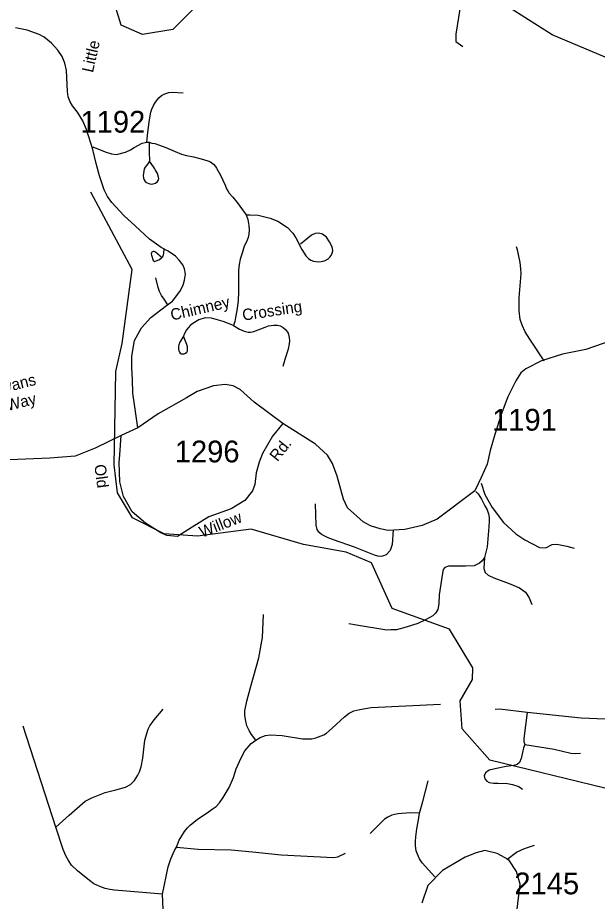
# Model space of a CAD drawing. Extents: x 884530 to 1028605, y 526725 to 653634.
# Drawn here: x 952140 to 955468, y 574776 to 579851 of the extents above; entities that cross this region are included whole.
import ezdxf

# ---------------------------------------------------------------- set-up
doc = ezdxf.new("R2010")
doc.units = 0
for name, color, linetype in [('Exist Hydrographic Creek Single Shore', 7, 'Continuous'), ('Exist Road Non-System Type 51', 7, 'Continuous'), ('Exist Road Non-System Type 51 Label', 7, 'Continuous'), ('Exist Road Secondary Type 41 Attributed', 7, 'Continuous'), ('Exist Road Secondary Type 51 Attributed', 7, 'Continuous'), ('Exist Road Secondary Type 51 Label', 7, 'Continuous'), ('Exist Road Secondary Type 51 Number Label', 7, 'Continuous')]:
    doc.layers.add(name, color=color, linetype=linetype)

msp = doc.modelspace()

# ---------------------------------------------------------------- linework, layer by layer
at = {"layer": 'Exist Hydrographic Creek Single Shore'}
for points in [[(955878.1, 579595.1), (955513.6, 579625.4), (955209.6, 579752.9), (954973.2, 579902.1), (954735.2, 580011.9), (954544.8, 580051.7), (954430.4, 580113.1), (954046.2, 580101.2), (953855.9, 580141.1), (953455.4, 580132.7), (953328.8, 580086.1), (953031.5, 579784.1), (952856.8, 579755.7), (952734, 579807.7), (952630.2, 580147.8), (952328, 580525.7), (951709.5, 580686.3), (951128.8, 580771.3)], [(955732, 575371.2), (954851.6, 575585.8), (954691.4, 575766.3), (954680.5, 575927.2), (954751.5, 576050.5), (954753.8, 576116.1), (954620.1, 576338.7), (954290.9, 576456.9), (954171.2, 576719.5), (954027.2, 576780.9), (953781.7, 576825.8), (953481.6, 576912.9), (953171.8, 576873.1), (952980.5, 576886.8), (952800.2, 576979.1), (952713.6, 577122), (952694.3, 577283.1), (952701.2, 577706.4), (952702.9, 577818.5), (952740.6, 577979.1), (952797.3, 578404.3), (952561.2, 578848.3)]]:
    msp.add_lwpolyline(points, dxfattribs=at)
at = {"layer": 'Exist Road Non-System Type 51'}
for p, q in [((952881.4, 579136.9), (952895, 579135.5)), ((952359.8, 575202.4), (952171.4, 575782.6))]:
    msp.add_line(p, q, dxfattribs=at)
for points in [[(952881.4, 579136.9), (952885.5, 579174.9), (952894.9, 579253.9), (952904.8, 579308), (952910.8, 579325.7), (952920.2, 579347.6), (952931.1, 579366.2), (952949.9, 579390.5), (952966.1, 579405.3), (952985.1, 579414.7), (953008, 579421.5), (953026.9, 579424.2), (953090.4, 579418.8)], [(952571.7, 579110.2), (952642.5, 579080.8), (952679.8, 579069), (952707.7, 579065.5), (952760, 579078.6), (952787.8, 579092.5), (952808.9, 579105.3), (952855.2, 579130.8), (952871.7, 579135.3), (952881.4, 579136.9)], [(952895, 579135.5), (952894.8, 579081.4), (952896.6, 579026.5), (952892.2, 579018.4), (952887.9, 579011.8), (952880.5, 579003.1), (952872.4, 578992.8), (952866.8, 578982.9), (952862, 578955.4), (952861.7, 578943.9), (952863.4, 578929.3), (952866, 578919.8), (952872.7, 578911.2), (952883, 578902.8), (952892.7, 578898.8), (952899.6, 578896.6), (952907.9, 578895.1), (952918, 578896.7), (952930.7, 578901.2), (952942.9, 578910.9), (952947, 578915.9), (952949.3, 578921.4), (952950.1, 578928.1), (952949.4, 578935.1), (952942.9, 578956.2), (952932.3, 578975.6), (952928.3, 578983.4), (952923.9, 578989.5), (952919.8, 578994.8), (952896.6, 579026.5)], [(952895, 579135.5), (952909.9, 579131.4), (952926.8, 579127.7), (952955, 579119.6), (952990.5, 579105.8), (953043.9, 579083.2), (953081.2, 579067.8), (953110, 579060.3), (953149.9, 579052.4), (953194.3, 579040.3), (953231.6, 579029.8), (953247.3, 579022.8), (953264.4, 579010.7), (953275.9, 578997.4), (953282.5, 578987.4), (953304.4, 578946.5), (953330.9, 578888.4), (953340, 578868.2), (953347.4, 578856.3), (953354.7, 578844.1), (953374.7, 578819.6), (953400.2, 578790.4), (953431.8, 578748.2), (953453, 578718.7)], [(953453, 578718.7), (953461.2, 578691.7), (953468.2, 578658.5), (953469.8, 578633.5), (953467, 578608.6), (953462.9, 578588.5), (953453.8, 578564.3), (953441.3, 578538.5), (953429.1, 578498.6), (953417.9, 578464.8), (953411.7, 578433.7), (953408.8, 578399.7), (953407.6, 578337.5), (953408, 578272.8), (953406.8, 578229.3), (953400.2, 578181), (953391.2, 578129), (953387.7, 578106.6), (953378.9, 578084)], [(953453, 578718.7), (953474.7, 578718.4), (953521.5, 578716.5), (953589.1, 578700.7), (953633.6, 578681.9), (953688.9, 578645.7), (953720.1, 578614.5), (953737.3, 578587.4), (953772.4, 578518.9), (953795.2, 578482.6), (953810.2, 578468), (953824, 578458.2), (953837.8, 578453), (953852.1, 578451.4), (953866.7, 578449.8), (953882.9, 578450.1), (953895.1, 578452.5), (953905.8, 578457.1), (953922, 578466.8), (953932.9, 578475.8), (953939.9, 578485), (953946, 578498.5), (953948.8, 578512.7), (953948.4, 578524.9), (953943.9, 578539.6), (953931.3, 578563.9), (953912.6, 578591.2), (953889.9, 578608.7), (953867.9, 578614.4), (953847.6, 578612.3), (953827.2, 578602.2), (953764.4, 578551.1)], [(952979.8, 578521.7), (952977.3, 578500.6), (952975.7, 578487.5), (952974.2, 578481.3), (952969.4, 578475.6), (952962.5, 578478.6), (952957.7, 578481.6), (952932, 578504), (952927.8, 578506.5), (952923.8, 578507.7), (952918.5, 578507.4), (952914.4, 578506.3), (952911.2, 578504.3), (952908.6, 578501.5), (952907.3, 578494.9), (952907.7, 578487.5), (952917.8, 578457.2), (952919.5, 578454), (952921.4, 578452.1), (952923.5, 578451.4), (952926.2, 578451), (952929.5, 578451.8), (952941.8, 578457.4), (952953.6, 578463.1), (952969.4, 578475.6)], [(955163.7, 577879.7), (955163.6, 577880), (955081.1, 578004.8), (955054.5, 578046.9), (955036.1, 578086), (955024.6, 578117.7), (955018.6, 578167), (955018.6, 578241.8), (955028.5, 578356.6), (955030.7, 578382.9), (955029.5, 578406.5), (955027, 578427.6), (955024.5, 578445.1), (955010.8, 578517.2), (955004.5, 578534.6)], [(953002.8, 578201), (952981.1, 578233.8), (952966, 578256.1), (952953.6, 578277.7), (952946.3, 578302), (952932.6, 578357.8)], [(953378.9, 578084), (953319.4, 578107), (953253.4, 578125.6), (953216.9, 578127.7), (953181, 578116.3), (953145.1, 578094.9), (953131.3, 578083.5), (953121.1, 578072.5), (953110.4, 578058), (953098, 578037.1), (953091.7, 578021.6), (953070.9, 577987.2), (953066, 577972.9), (953063.2, 577959.8), (953063.5, 577947.1), (953065.6, 577937.3), (953068.9, 577929.9), (953073, 577923.8), (953078.3, 577921.3), (953085.3, 577920.1), (953096.2, 577920.9), (953104.6, 577924.7), (953111.9, 577930.7), (953114.4, 577937.3), (953116, 577948), (953114.8, 577961.5), (953110.6, 577974.6), (953091.7, 578021.6)], [(953378.9, 578084), (953414.6, 578061.4), (953440.3, 578049.9), (953464.1, 578045), (953477.2, 578045.8), (953496.4, 578047.9), (953561.2, 578072.9), (953580.4, 578080.6), (953611.5, 578086), (953632.4, 578085.1), (953648, 578081), (953664.3, 578071.6), (953679.5, 578058.6), (953692.6, 578038.8), (953699.6, 578014.3), (953701.2, 577995.4), (953699.6, 577977.9), (953693.9, 577946.7), (953674.7, 577887.7), (953663.1, 577848)], [(954801.5, 577177.6), (954821.6, 577113.4), (954863.8, 577037.1), (954930, 576951.8), (955000.2, 576886.6), (955051.4, 576852.4), (955136.7, 576808.3), (955171.9, 576806.2), (955209, 576824.7), (955236.2, 576827.4), (955292.3, 576816.3), (955334.5, 576803.3)], [(954771.4, 577129.2), (954783.4, 577115.4), (954802.5, 577086.3), (954822.7, 577048.2), (954836.6, 577024), (954843.8, 577001), (954847.7, 576980), (954848.2, 576960.9), (954845.7, 576926.7), (954835.6, 576812.3), (954819.6, 576751.1)], [(954295.7, 576909.6), (954289.6, 576824.3), (954279.6, 576790.2), (954255.5, 576766.1), (954235.4, 576758.1), (954224.3, 576756), (954207.3, 576759.1), (954188.2, 576763.1), (954073.9, 576810.3), (953953.3, 576851.4), (953922.3, 576863.5), (953885.2, 576883.6), (953870.1, 576895.6), (953860.1, 576911.7), (953853.1, 576936.7), (953851, 577058.2)], [(954819.6, 576751.1), (954806.6, 576732), (954791.5, 576718), (954761.4, 576702.9), (954712.1, 576699.9), (954613.8, 576699.9), (954592.7, 576693.9), (954583.8, 576681.8), (954579.7, 576660.7), (954567.7, 576585.4), (954559.6, 576536.2), (954558.7, 576484), (954551.6, 576452), (954539.6, 576430.9), (954523.5, 576415.8), (954481.4, 576391.8), (954437.2, 576370.7), (954369.9, 576349.6), (954314.8, 576335.6), (954283.6, 576334.6), (954259.5, 576333.6), (954084.9, 576362.6), (954041.7, 576368.7)], [(954819.6, 576751.1), (954816.5, 576687.8), (954824.6, 576663.8), (954841.7, 576648.7), (954873.8, 576634.6), (954962.1, 576601.5), (955021.4, 576576.4), (955056.4, 576551.3), (955077.5, 576518.2), (955092.6, 576480)], [(953508.4, 575702.1), (953483, 575734.3), (953469.4, 575757.7), (953456.6, 575783.4), (953449.5, 575810.5), (953444.5, 575843.4), (953443.8, 575870.4), (953455.2, 575926), (953476.6, 576004.5), (953525.1, 576174.3), (953545.1, 576291.2), (953552.2, 576422.4)], [(953508.4, 575702.1), (953532.6, 575716.4), (953562.6, 575728.4), (953591.6, 575732.3), (953658.5, 575727.3), (953776.4, 575709.2), (953828.8, 575709.4), (953851.8, 575714.2), (953897.7, 575731.5), (953913.2, 575740.8), (953945.7, 575770.3), (954017.1, 575834.8), (954044.3, 575856.2), (954069.9, 575869), (954105.6, 575877.5), (954169.8, 575889), (954567.7, 575907.5)], [(952359.8, 575202.4), (952435.9, 575270.9), (952528.3, 575350.3), (952566.2, 575370.9), (952643.4, 575400.2), (952703.7, 575416.6), (952758.4, 575431.2), (952788.6, 575447.6), (952810.4, 575470.4), (952829.7, 575499.7), (952840.5, 575518.8), (952849.7, 575549), (952858.8, 575598.3), (952869.8, 575700.5), (952888.9, 575764.4), (952899.9, 575784.5), (952924.6, 575817.3), (952974.7, 575879.4)], [(955065.3, 575860.9), (954906.5, 575879.7), (954880.9, 575876.7)], [(955065.3, 575860.9), (955045.7, 575710), (955046.6, 575693.2), (955052.5, 575676.4)], [(955838.9, 575809.1), (955374.6, 575828.6), (955065.3, 575860.9)], [(953052.4, 575086.1), (953066.9, 575127.3), (953098.5, 575176.8), (953115.3, 575197.5), (953131.4, 575213.4), (953172.8, 575246.8), (953228.5, 575283.3), (953257.7, 575305.2), (953279.7, 575319.8), (953299.7, 575341.7), (953319.8, 575371.9), (953355.4, 575429.4), (953379.1, 575486.9), (953395.6, 575537.1), (953423, 575600.1), (953445.1, 575639.4), (953481.6, 575681.8), (953508.4, 575702.1)], [(955052.5, 575676.4), (955043.6, 575656.8), (955038.8, 575631.1), (955031.8, 575595.6), (955021.8, 575573.9), (955007.2, 575562), (954988.5, 575555.2), (954944, 575549.1), (954888.6, 575538.1), (954847.6, 575528.6), (954825.3, 575514.4), (954819.1, 575496.9), (954821.6, 575479.1), (954833.5, 575465.3), (954847.6, 575457.4), (954872, 575453.5), (954899.7, 575454.4), (954952, 575451.5), (954981.5, 575447.6), (955017.1, 575434.7), (955038.8, 575419.9)], [(955052.5, 575676.4), (955220.3, 575649.8), (955316, 575626.1), (955344.5, 575625.1), (955372.2, 575626.1)], [(954447.2, 575282.5), (954465.5, 575349.9), (954496.4, 575468.1)], [(954447.2, 575282.5), (954393.3, 575283.3), (954322.8, 575277.8), (954288.7, 575270.6), (954264.8, 575258.7), (954246.6, 575246.8), (954235.6, 575236.5), (954164.1, 575165.9)], [(954534.5, 574916.9), (954463.1, 574996.2), (954448, 575020), (954436.1, 575046.2), (954429, 575066), (954425.1, 575093.7), (954425, 575118.4), (954426.6, 575146.1), (954432.1, 575192.1), (954440.1, 575232.6), (954447.2, 575282.5)], [(952971.9, 574816.1), (952696.2, 574840.4), (952669, 574843.7), (952641.9, 574849.3), (952612, 574860.1), (952576.9, 574875.9), (952551.7, 574895.1), (952484.5, 574949.8), (952449.4, 574983), (952432.1, 575010.5), (952417.6, 575036.7), (952402.2, 575073.6), (952359.8, 575202.4)], [(954948.5, 575016.4), (955003.9, 575057.2), (955050.6, 575078.7), (955108.1, 575098.4)], [(952971.9, 574816.1), (953004.7, 574974.4), (953020.4, 575020.4), (953040.5, 575067.9), (953052.4, 575086.1)], [(953052.4, 575086.1), (953175.6, 575075.2), (953365.2, 575070.6), (953489.4, 575060.1), (953652.1, 575042.6), (953953.1, 575026.9), (953977.9, 575030.4), (954023.2, 575053.1)], [(953033.6, 574314.8), (953036.4, 574361.2), (953017.7, 574462.3), (953003.1, 574526.8), (952989.2, 574597.4), (952980.8, 574653.5), (952975.1, 574729.2), (952971.9, 574816.1)]]:
    msp.add_lwpolyline(points, dxfattribs=at)
at = {"layer": 'Exist Road Secondary Type 41 Attributed'}
for points in [[(952571.8, 579093.5), (952534.7, 579210), (952514.2, 579259.4), (952483.1, 579308.7), (952455.8, 579345.5), (952441.4, 579368.3), (952430.7, 579397.1), (952426.9, 579427.5), (952420.1, 579548.9), (952411.8, 579590.3), (952395.8, 579629), (952371.6, 579663.9), (952333.6, 579704.1), (952292.7, 579739), (952264.1, 579755), (952194.8, 579778.9), (952128, 579793.3)], [(953662, 577519.6), (953604.1, 577447.3), (953545.3, 577347.6), (953526.2, 577297.4), (953509.9, 577236.5), (953502, 577169.8), (953488.1, 577133.3), (953444.9, 577077.3), (953366, 577029.5), (953236.9, 576984), (953141.3, 576924.2), (953057.6, 576871.6), (952996.8, 576877.9), (952962, 576893.1), (952875, 576947.4), (952797.1, 577012.7), (952746.9, 577101.2), (952727.7, 577184.5), (952723, 577297.1), (952726, 577339.6), (952734.8, 577451)]]:
    msp.add_lwpolyline(points, dxfattribs=at)
at = {"layer": 'Exist Road Secondary Type 51 Attributed'}
msp.add_line((952830.5, 577496.2), (952734.8, 577451), dxfattribs=at)
for points in [[(954684.7, 579936), (954655.9, 579756.1), (954656.2, 579714.1), (954696.9, 579686.3)], [(952830.5, 577496.2), (952812.3, 577616.2), (952801.7, 577693.6), (952798.7, 577772.5), (952795.6, 577839.3), (952795.6, 577907.6), (952810.8, 577997.9), (952851.8, 578069.7), (952904.9, 578128.9), (952994.4, 578197.2), (953029.3, 578222.6), (953071.5, 578277.6), (953090.8, 578315.2), (953098.4, 578344), (953102.9, 578378.2), (953097.6, 578407.8), (953088.5, 578432.4), (953067.5, 578458), (953046, 578481.8), (953005.1, 578510.3), (952964.1, 578531.9), (952896.6, 578579.7), (952814.1, 578655.6), (952749.4, 578715.5), (952680.3, 578789.2), (952656.1, 578824.8), (952637.2, 578862.7), (952610.5, 578943.6), (952590.8, 579014.2), (952571.8, 579093.5)], [(955738.9, 578061.6), (955402.4, 577945.2), (955267.7, 577918), (955147.9, 577880.9), (955058.1, 577834.2), (955030, 577811.1), (954999.9, 577765.8), (954955.1, 577673.5), (954916.9, 577571.9), (954879.2, 577457.1), (954853, 577364.4), (954835, 577287.3), (954802, 577209.2), (954765, 577133.9), (954548.9, 576969.9), (954462.7, 576934.4), (954362.4, 576910.8), (954267.9, 576906.1), (954220.7, 576915.6), (954166.4, 576932.1), (954124, 576955.7), (954034.2, 577036), (954010.6, 577085.6), (953975.2, 577217.9), (953946.9, 577291.1), (953918.6, 577338.3), (953850.1, 577402.1), (953662, 577519.6)], [(953662, 577519.6), (953587.9, 577575), (953498.3, 577642.8), (953417.7, 577714.8), (953378.3, 577736.1), (953331.3, 577743.7), (953264.5, 577737.6), (953170.4, 577704.2), (953110.1, 577667.7), (952947.2, 577575.6), (952830.5, 577496.2)], [(952734.8, 577451), (952585, 577377.9), (952471.1, 577332.3), (952325.4, 577320.9), (952045.4, 577309.5)], [(955004.5, 574699.2), (955025.7, 574873.9), (955004.5, 574947.2), (954959.6, 575013.3), (954893.5, 575051.1), (954822.7, 575067.6), (954773.1, 575053.4), (954709.4, 575029.8), (954579.5, 574951.9), (954494.6, 574867.3), (954461.5, 574765.3)]]:
    msp.add_lwpolyline(points, dxfattribs=at)

# ---------------------------------------------------------------- texts
at = {"layer": 'Exist Road Non-System Type 51 Label'}
for s, rotation, p in [('Little', 77.2848, (952572.1, 579532.4)), ('Chimney', 12.9987, (953025.8, 578111.1)), ('Crossing', 8.749, (953434.9, 578110.4)), ('Evans', 14.0407, (952014, 577684.4)), ('Way', 14.0407, (952082.1, 577591.4))]:
    msp.add_text(s, height=65.62, rotation=rotation, dxfattribs=at).set_placement(p)
at = {"layer": 'Exist Road Secondary Type 51 Label'}
for s, rotation, p in [('Rd.', 51.4011, (953631.6, 577297.8)), ('Old', 277.5524, (952579.9, 577281.3)), ('Willow', 21.4984, (953198.6, 576863.5))]:
    msp.add_text(s, height=65.62, rotation=rotation, dxfattribs=at).set_placement(p)
at = {"layer": 'Exist Road Secondary Type 51 Number Label'}
for s, p in [('1192', (952500.9, 579191.1)), ('1191', (954864, 577479.3)), ('1296', (953042.1, 577297)), ('2145', (954992, 574815.9))]:
    msp.add_text(s, height=125, dxfattribs=at).set_placement(p)

doc.saveas('drawing.dxf')
